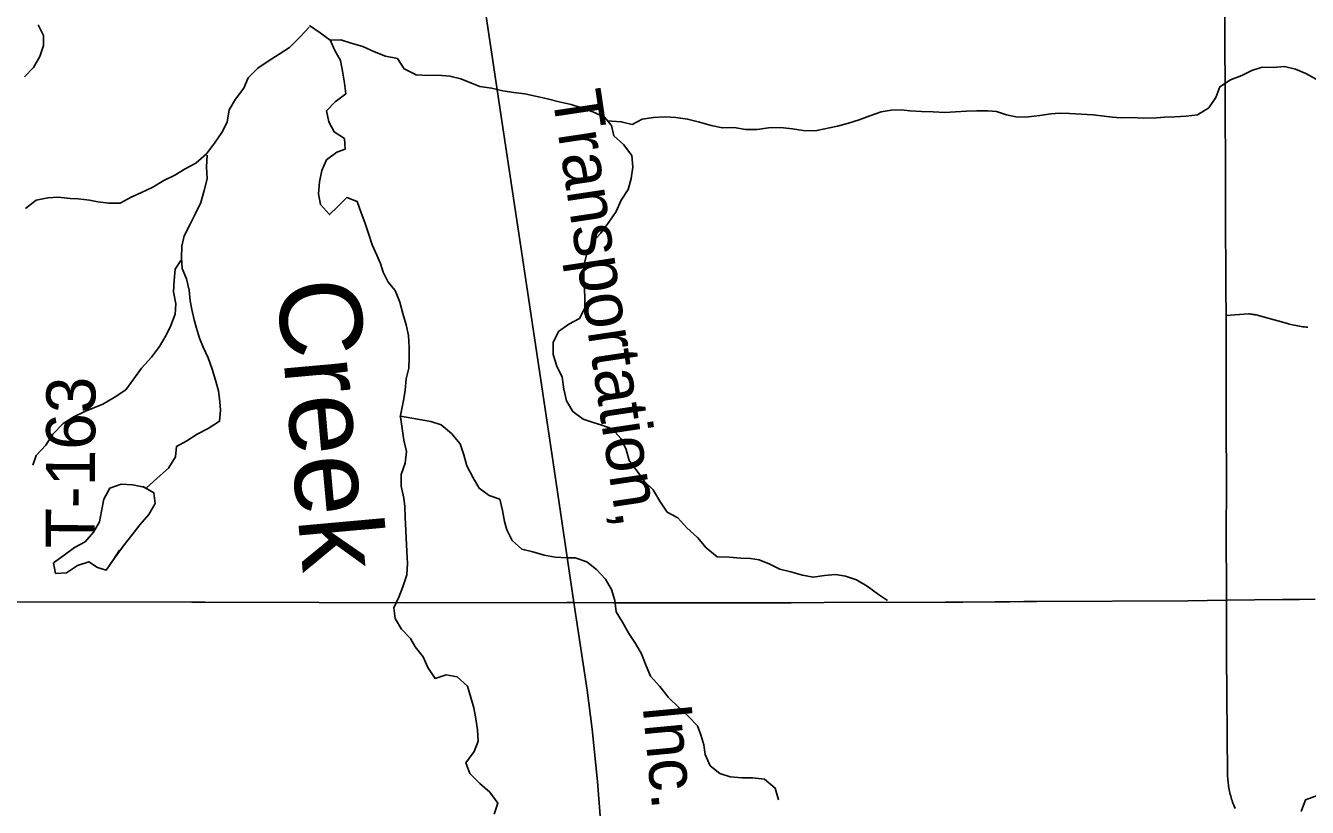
# Model space of a CAD drawing. Extents: x 0 to 34, y 0 to 22.
# Drawn here: x 2.378 to 3.119, y 16.133 to 16.585 of the extents above; entities that cross this region are included whole.
import ezdxf

# ---------------------------------------------------------------- set-up
doc = ezdxf.new("R2010")
doc.units = 0
for name, color, linetype in [('GM_X_County_Road', 7, 'Continuous'), ('GM_X_Minor_Lake', 7, 'Continuous'), ('GM_X_Minor_River', 7, 'Continuous'), ('GM_X_Minor_River_Text', 7, 'Continuous'), ('GM_X_Rail_Line', 7, 'Continuous'), ('GM_X_Rail_Line_Text', 7, 'Continuous'), ('GM_X_Township_Road', 7, 'Continuous'), ('GM_X_Township_Road_Text', 7, 'Continuous')]:
    doc.layers.add(name, color=color, linetype=linetype)

msp = doc.modelspace()

# ---------------------------------------------------------------- linework, layer by layer
at = {"layer": 'GM_X_County_Road'}
msp.add_lwpolyline([(3.07753, 16.13207), (3.07716, 16.13295), (3.07681, 16.13384), (3.07648, 16.13472), (3.07616, 16.13562), (3.07586, 16.13652), (3.07557, 16.13743), (3.0753, 16.13834), (3.07504, 16.13925), (3.0748, 16.14017), (3.07458, 16.1411), (3.07437, 16.14202), (3.07419, 16.14295), (3.07401, 16.14389), (3.07385, 16.14482), (3.07371, 16.14577), (3.07358, 16.14671), (3.07347, 16.14765), (3.07338, 16.1486), (3.07331, 16.14954), (3.07325, 16.15049), (3.0732, 16.15144), (3.07258, 16.22102), (3.07253, 16.25241), (3.07249, 16.29575), (3.07258, 16.31424), (3.0724, 16.36098), (3.07231, 16.3971), (3.0724, 16.40923), (3.07244, 16.41722), (3.07226, 16.43244), (3.07217, 16.44862), (3.07203, 16.46279), (3.07194, 16.49509), (3.07181, 16.54411), (3.07176, 16.55528), (3.07167, 16.56846), (3.07176, 16.62869)], dxfattribs=at)
at = {"layer": 'GM_X_Minor_Lake'}
for points in [[(2.44686, 16.31783), (2.44018, 16.3193), (2.43371, 16.31966), (2.42707, 16.31735), (2.42368, 16.31087), (2.42219, 16.30402), (2.42108, 16.29774), (2.41769, 16.29184), (2.41277, 16.2863), (2.40671, 16.28305), (2.40065, 16.27847), (2.39459, 16.27407), (2.39575, 16.26799), (2.40202, 16.26839), (2.40846, 16.2726), (2.41492, 16.27471), (2.41987, 16.2713), (2.42501, 16.2698), (2.42878, 16.27552), (2.43483, 16.28371)], [(2.44702, 16.3178), (2.44018, 16.3193), (2.43371, 16.31966), (2.42707, 16.31735), (2.42368, 16.31087), (2.42219, 16.30402), (2.42108, 16.29774), (2.41769, 16.29184), (2.41277, 16.2863), (2.40671, 16.28305), (2.40065, 16.27847), (2.39459, 16.27407), (2.39575, 16.26799), (2.40202, 16.26839), (2.40846, 16.2726), (2.41492, 16.27471), (2.41987, 16.2713), (2.42501, 16.2698), (2.42878, 16.27552), (2.43275, 16.28143)], [(2.43483, 16.28371), (2.43974, 16.29001), (2.44446, 16.29611), (2.44956, 16.30202), (2.45333, 16.3085), (2.45255, 16.31458), (2.44626, 16.31818)], [(2.43483, 16.28371), (2.43974, 16.29001), (2.44446, 16.29611), (2.44956, 16.30202), (2.45333, 16.3085), (2.45255, 16.31458), (2.44686, 16.31783)]]:
    msp.add_lwpolyline(points, dxfattribs=at)
at = {"layer": 'GM_X_Minor_River'}
for points in [[(2.38558, 16.58537), (2.38883, 16.5791), (2.38867, 16.5734), (2.38661, 16.56693), (2.38303, 16.56064), (2.37773, 16.55529)], [(2.54234, 16.58398), (2.53705, 16.57826), (2.531, 16.57215), (2.52493, 16.56833), (2.51868, 16.56432), (2.51262, 16.5603), (2.50713, 16.55458), (2.5045, 16.54868), (2.49978, 16.54238), (2.49601, 16.5361), (2.4949, 16.52905), (2.49189, 16.52296), (2.48754, 16.51686), (2.48301, 16.51076), (2.47676, 16.50522), (2.4707, 16.50197), (2.46464, 16.49834), (2.45838, 16.49527), (2.45194, 16.49145), (2.44549, 16.48839), (2.43942, 16.4857), (2.43298, 16.48207), (2.42652, 16.48205), (2.42024, 16.48298), (2.4153, 16.48391), (2.40883, 16.48465), (2.40408, 16.48483), (2.39724, 16.48556), (2.39116, 16.48516), (2.38452, 16.48381), (2.37827, 16.47903)], [(2.54256, 16.58483), (2.54861, 16.58061), (2.55448, 16.57639)], [(2.59489, 16.35836), (2.59713, 16.36901), (2.59773, 16.37395), (2.59833, 16.38061), (2.59988, 16.38668), (2.6001, 16.39258), (2.60013, 16.39867), (2.59978, 16.40552), (2.5983, 16.4118), (2.59643, 16.41828), (2.59475, 16.42495), (2.59194, 16.43162), (2.58797, 16.4364), (2.58515, 16.44231), (2.58347, 16.44727), (2.5814, 16.45203), (2.57877, 16.45794), (2.57653, 16.46461), (2.57447, 16.4709), (2.57241, 16.47662), (2.57016, 16.4831), (2.5641, 16.48542), (2.55875, 16.47993), (2.55398, 16.47558), (2.54888, 16.48132), (2.54777, 16.4876), (2.54838, 16.49444), (2.54955, 16.50109), (2.55243, 16.50717), (2.55834, 16.5117), (2.56309, 16.51338), (2.56274, 16.51947), (2.55669, 16.52331), (2.55368, 16.52922), (2.55238, 16.53551), (2.55734, 16.54081), (2.56344, 16.54534), (2.56271, 16.55162), (2.56161, 16.55847), (2.5605, 16.56457), (2.55692, 16.57086), (2.55448, 16.57658)], [(2.55444, 16.57638), (2.56056, 16.57655), (2.56663, 16.57461), (2.57326, 16.57267), (2.58008, 16.56959), (2.58653, 16.56708), (2.59336, 16.5659), (2.59732, 16.5598), (2.60414, 16.55633), (2.61059, 16.55592), (2.61667, 16.55626), (2.6237, 16.55566), (2.62996, 16.5541), (2.63621, 16.55159), (2.64095, 16.54966), (2.64778, 16.54867), (2.65423, 16.54712), (2.66069, 16.54613), (2.66695, 16.54533), (2.67321, 16.54397), (2.68004, 16.54241), (2.68687, 16.54066), (2.6937, 16.53929), (2.69977, 16.53735), (2.70621, 16.53503), (2.71303, 16.53195), (2.717, 16.52699), (2.71849, 16.52108), (2.72397, 16.5161), (2.72888, 16.5098), (2.72941, 16.50295), (2.72843, 16.49649), (2.72669, 16.49003), (2.72267, 16.48396), (2.71979, 16.47732), (2.71558, 16.47107), (2.7108, 16.46463), (2.70565, 16.45914), (2.70257, 16.45231), (2.70102, 16.44585), (2.70118, 16.43938), (2.70135, 16.43463), (2.70169, 16.42816), (2.70166, 16.42131), (2.69859, 16.41543), (2.6925, 16.41223), (2.6864, 16.40789), (2.68333, 16.40163), (2.6833, 16.39459), (2.68554, 16.38792), (2.68855, 16.38144), (2.68946, 16.37458), (2.69114, 16.36773), (2.69472, 16.36162), (2.70077, 16.35721), (2.70646, 16.35528), (2.71158, 16.35373), (2.71746, 16.3516), (2.72256, 16.34606), (2.72556, 16.33957), (2.72724, 16.33329), (2.73196, 16.32717), (2.73611, 16.32106), (2.74121, 16.31628), (2.74498, 16.30979), (2.74931, 16.3033), (2.75538, 16.30003), (2.76067, 16.2943), (2.76672, 16.28875), (2.77181, 16.28282), (2.77825, 16.27765), (2.78508, 16.27742), (2.79192, 16.27681), (2.79742, 16.27659), (2.80236, 16.2758), (2.80861, 16.2733), (2.81448, 16.27041), (2.82074, 16.26885), (2.82757, 16.26691), (2.83364, 16.26574), (2.8403, 16.26684), (2.84657, 16.26738), (2.85245, 16.26639), (2.85871, 16.26427), (2.86496, 16.26062), (2.87139, 16.25583), (2.87669, 16.25237)], [(2.71466, 16.52981), (2.72271, 16.52924), (2.72897, 16.52768), (2.73487, 16.53069), (2.74133, 16.5316), (2.74817, 16.53214), (2.75424, 16.53172), (2.76108, 16.53073), (2.76791, 16.52899), (2.77473, 16.52705), (2.78118, 16.52568), (2.78802, 16.52583), (2.79447, 16.52484), (2.80131, 16.52481), (2.80777, 16.52572), (2.8148, 16.52587), (2.82164, 16.52507), (2.8279, 16.52409), (2.83473, 16.52405), (2.84766, 16.52664), (2.85413, 16.52832), (2.86021, 16.53038), (2.86649, 16.53262), (2.87296, 16.53506), (2.87867, 16.53598), (2.88474, 16.53614), (2.88949, 16.53554), (2.89632, 16.53512), (2.90297, 16.53489), (2.90981, 16.53467), (2.91589, 16.53501), (2.92234, 16.53536), (2.92823, 16.53552), (2.93469, 16.53548), (2.93963, 16.53507), (2.9455, 16.53314), (2.95176, 16.53196), (2.95822, 16.53212), (2.96468, 16.53284), (2.97096, 16.53376), (2.97609, 16.53411), (2.98178, 16.53408), (2.99545, 16.53324), (3.00191, 16.53244), (3.00665, 16.53185), (3.0114, 16.53144), (3.01767, 16.5316), (3.02469, 16.53137), (3.0321, 16.53152), (3.03685, 16.53187), (3.04274, 16.53203), (3.0492, 16.53237), (3.05585, 16.53329), (3.06233, 16.53725), (3.06634, 16.54331), (3.06865, 16.54939), (3.07494, 16.55354), (3.08141, 16.55597), (3.08731, 16.55879), (3.09321, 16.56085), (3.09967, 16.56063), (3.10613, 16.56116), (3.11258, 16.5596), (3.11845, 16.5571), (3.12451, 16.55383)], [(2.48339, 16.51), (2.48305, 16.50315), (2.48327, 16.49631), (2.48159, 16.48945), (2.47972, 16.4826), (2.47671, 16.47613), (2.47332, 16.46965), (2.47012, 16.46317), (2.46881, 16.45727), (2.46846, 16.4508), (2.46887, 16.44434), (2.47137, 16.43845), (2.47292, 16.4318), (2.47352, 16.42572), (2.47449, 16.42059), (2.47585, 16.41469), (2.4772, 16.40975), (2.47893, 16.40405), (2.48105, 16.39893), (2.48393, 16.39266), (2.48624, 16.3862), (2.48816, 16.37974), (2.4899, 16.37366), (2.49069, 16.3672), (2.49109, 16.36244), (2.49055, 16.35598), (2.48392, 16.35177), (2.47767, 16.34852), (2.4716, 16.34469), (2.46554, 16.34144), (2.46499, 16.33535), (2.46103, 16.32887), (2.45441, 16.32315), (2.44835, 16.31742)], [(2.46809, 16.4489), (2.46488, 16.44395), (2.46434, 16.43748), (2.46399, 16.43082), (2.46516, 16.42398), (2.46481, 16.41789), (2.46237, 16.41142), (2.45974, 16.4057), (2.45577, 16.39922), (2.45124, 16.39312), (2.44538, 16.38664), (2.44104, 16.38054), (2.43632, 16.37425), (2.42969, 16.36966), (2.42305, 16.36584), (2.41831, 16.36392), (2.41262, 16.36162), (2.40637, 16.35855), (2.40011, 16.35473), (2.39406, 16.34843), (2.3901, 16.34214), (2.38442, 16.33623), (2.38255, 16.33052)], [(2.64931, 16.12866), (2.65143, 16.13512), (2.64671, 16.14142), (2.64104, 16.1464), (2.63518, 16.15214), (2.63293, 16.15843), (2.63771, 16.16487), (2.64002, 16.17094), (2.63968, 16.17741), (2.63876, 16.18389), (2.63746, 16.19017), (2.63578, 16.19627), (2.63391, 16.20274), (2.62786, 16.2081), (2.6216, 16.20928), (2.61513, 16.20722), (2.61099, 16.21352), (2.60817, 16.21963), (2.60364, 16.22555), (2.60081, 16.23032), (2.59571, 16.23567), (2.59195, 16.24197), (2.59122, 16.24806), (2.5941, 16.25414), (2.5964, 16.26021), (2.59872, 16.26723), (2.59913, 16.2737), (2.59878, 16.28055), (2.59774, 16.30053), (2.59758, 16.30662), (2.59704, 16.31156), (2.59555, 16.31842), (2.59559, 16.32527), (2.5979, 16.33172), (2.5985, 16.33857), (2.59701, 16.34504), (2.5961, 16.35171), (2.59518, 16.35856)], [(2.59509, 16.35896), (2.60619, 16.35698), (2.61264, 16.3558), (2.61871, 16.35386), (2.62457, 16.34888), (2.62967, 16.34296), (2.63173, 16.33648), (2.63341, 16.33019), (2.63717, 16.32333), (2.64056, 16.31722), (2.64643, 16.313), (2.65249, 16.31088), (2.65417, 16.3044), (2.65528, 16.29793), (2.65658, 16.29316), (2.65959, 16.28706), (2.66526, 16.28208), (2.67152, 16.28053), (2.67816, 16.27859), (2.68461, 16.27741), (2.69126, 16.27699), (2.69601, 16.27696), (2.70283, 16.27464), (2.70851, 16.27024), (2.71361, 16.26469), (2.717, 16.25859), (2.71905, 16.2523), (2.71978, 16.24583), (2.72336, 16.23972), (2.72713, 16.23323), (2.7309, 16.2275), (2.73448, 16.2214), (2.7371, 16.21453), (2.73954, 16.20862), (2.74502, 16.20251), (2.75011, 16.1962), (2.75597, 16.19046), (2.76164, 16.1851), (2.76674, 16.17975), (2.76881, 16.1746), (2.77049, 16.16889), (2.77122, 16.16318), (2.77404, 16.15669), (2.77971, 16.15229), (2.78578, 16.15035), (2.79262, 16.14974), (2.79869, 16.14971), (2.80553, 16.14891), (2.81177, 16.14374), (2.81363, 16.13707)], [(3.11577, 16.13016), (3.11821, 16.13702), (3.13072, 16.14163)]]:
    msp.add_lwpolyline(points, dxfattribs=at)
at = {"layer": 'GM_X_Rail_Line'}
msp.add_lwpolyline([(2.71055, 16.1277), (2.70897, 16.14768), (2.70596, 16.17794), (2.70305, 16.20042), (2.69532, 16.2512), (2.68337, 16.33213), (2.67746, 16.37199), (2.6663, 16.44668), (2.65488, 16.52197), (2.63424, 16.65973), (2.63194, 16.68067), (2.6302, 16.69581), (2.62816, 16.7238), (2.62592, 16.76846), (2.62587, 16.9163), (2.62628, 17.02106), (2.6265, 17.04329)], dxfattribs=at)
at = {"layer": 'GM_X_Township_Road'}
for points in [[(3.07244, 16.41722), (3.08527, 16.41811), (3.08592, 16.41805), (3.08658, 16.41798), (3.08723, 16.4179), (3.08788, 16.41781), (3.08853, 16.41771), (3.08918, 16.4176), (3.08982, 16.41747), (3.09047, 16.41734), (3.09111, 16.41719), (3.09174, 16.41703), (3.09238, 16.41686), (3.10794, 16.41246), (3.1089, 16.41219), (3.10986, 16.41194), (3.11083, 16.41172), (3.1118, 16.4115), (3.11278, 16.4113), (3.11375, 16.41112), (3.11474, 16.41096), (3.11572, 16.41081), (3.11671, 16.41069), (3.1177, 16.41057), (3.11869, 16.41048), (3.11969, 16.4104)], [(2.37188, 16.25159), (2.47455, 16.25136), (2.482, 16.25127), (2.54801, 16.25118), (2.59916, 16.251), (2.69125, 16.25114), (2.69548, 16.25118), (2.71819, 16.25104), (2.78479, 16.25095), (2.82086, 16.251), (2.84003, 16.25109), (2.90999, 16.25136), (2.92021, 16.25141), (2.93884, 16.25154), (2.94719, 16.25159), (2.95551, 16.25163), (2.96296, 16.25168), (3.05032, 16.25218), (3.07253, 16.25241)], [(3.07253, 16.25241), (3.1049, 16.25283), (3.11487, 16.25291), (3.12385, 16.25299)]]:
    msp.add_lwpolyline(points, dxfattribs=at)

# ---------------------------------------------------------------- texts
at = {"layer": 'GM_X_Minor_River_Text'}
msp.add_text('Creek', height=0.047373, rotation=275.17089, dxfattribs=at).set_placement((2.52344, 16.43649))
at = {"layer": 'GM_X_Rail_Line_Text'}
for s, height, rotation, p in [('Transportation,', 0.0283144, 278.51019, (2.68265, 16.5455)), ('Inc.', 0.028314, 275.37604, (2.73502, 16.19145))]:
    msp.add_text(s, height=height, rotation=rotation, dxfattribs=at).set_placement(p)
at = {"layer": 'GM_X_Township_Road_Text'}
msp.add_text('T-163', height=0.028409, rotation=89.71928, dxfattribs=at).set_placement((2.41835, 16.28247))

doc.saveas('drawing.dxf')
